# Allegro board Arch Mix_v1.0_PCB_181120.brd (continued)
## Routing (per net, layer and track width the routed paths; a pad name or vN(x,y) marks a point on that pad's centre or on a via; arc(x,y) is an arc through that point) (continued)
SEMC_A10: length 35
  TOP w0.127: U8.G2 36.48,21.66 34.83,21.66 34.7,21.52 30.42,21.52 24.24,15.35 23.05,15.35 22.86,15.54 22.86,15.73 22.73,15.86 22.48,15.86 22.35,15.73 22.35,15.43 22.22,15.3 21.97,15.3 21.84,15.43 21.84,15.73 21.71,15.86 21.46,15.86 21.33,15.73 21.33,15.44 21.12,15.22 16.27,15.22 15.87,15.62 15.69,15.62 15.36,15.3 15.18,15.3 15,15.48 15,15.66 15.33,15.98 15.33,16.16 14.86,16.63 14.68,16.63 14.48,16.43 14.3,16.43 14.12,16.61 14.12,16.79 14.32,16.99 14.32,17.17 13.91,17.58 13.73,17.58 13.15,17 12.97,17 12.79,17.18 12.79,17.36 13.37,17.94 13.37,18.12 13.21,18.29 U4.H9
SEMC_A11: length 34.8
  TOP w0.127: U4.G2 13.58,26.39 13.58,26.6 13.58,26.6 13.58,28.64 14.59,29.65 28.23,29.65 28.38,29.5 28.38,29.29 28.53,29.14 28.74,29.14 28.89,29.29 28.89,29.5 29.04,29.65 29.43,29.65 29.58,29.5 29.58,29.29 29.73,29.14 29.94,29.14 30.09,29.29 30.09,29.5 30.24,29.65 30.45,29.65 30.6,29.5 30.6,29.29 30.74,29.14 30.96,29.14 31.1,29.29 31.1,29.5 31.25,29.65 31.46,29.65 31.61,29.5 31.61,29.29 31.76,29.14 31.97,29.14 32.12,29.29 32.12,29.5 32.27,29.65 32.48,29.65 32.63,29.5 32.63,29.29 32.78,29.14 32.99,29.14 33.14,29.29 33.14,29.5 33.28,29.65 33.5,29.65 33.64,29.5 33.64,29.29 33.79,29.14 34,29.14 34.15,29.29 34.15,29.5 34.3,29.65 34.65,29.65 37.77,26.53 37.77,24.92 U8.B4
SEMC_A12: length 34.5
  TOP w0.127: U4.G1 14.01,27.93 15.35,29.27 15.85,29.27 16,29.12 16,28.91 16.15,28.76 16.36,28.76 16.5,28.91 16.5,29.12 16.65,29.27 16.86,29.27 17.01,29.12 17.01,28.91 17.16,28.76 17.37,28.76 17.52,28.91 17.52,29.12 17.67,29.27 17.88,29.27 18.03,29.12 18.03,28.91 18.18,28.76 18.39,28.76 18.54,28.91 18.54,29.12 18.69,29.27 18.9,29.27 19.04,29.12 19.04,28.91 19.19,28.76 19.4,28.76 19.55,28.91 19.55,29.12 19.7,29.27 19.91,29.27 20.06,29.12 20.06,28.91 20.21,28.76 20.42,28.76 20.57,28.91 20.57,29.12 20.72,29.27 20.93,29.27 21.08,29.12 21.08,28.91 21.23,28.76 21.44,28.76 21.58,28.91 21.58,29.12 21.73,29.27 22.58,29.27 22.84,29.02 23.09,29.02 23.34,29.27 23.85,29.27 24,29.12 24,28.91 24.15,28.76 24.36,28.76 24.51,28.91 24.51,29.12 24.65,29.27 24.86,29.27 25.01,29.12 25.01,28.91 25.16,28.76 25.37,28.76 25.52,28.91 25.52,29.12 25.67,29.27 25.88,29.27 26.03,29.12 26.03,28.91 26.18,28.76 26.39,28.76 26.54,28.91 26.54,29.12 26.69,29.27 26.9,29.27 27.05,29.12 27.05,28.91 27.19,28.76 27.4,28.76 27.55,28.91 27.55,29.12 27.7,29.27 27.91,29.27 28.06,29.12 28.06,28.91 28.21,28.76 34.99,28.76 37.45,26.3 U8.A3
SEMC_BA0: length 35.1
  TOP w0.127: U4.G7 14.01,22.67 14.14,22.79 22.34,22.79 23.49,23.94 27.17,23.94 27.32,24.09 27.32,24.8 27.47,24.95 27.68,24.95 27.83,24.8 27.83,24.09 27.98,23.94 28.3,23.94 28.45,24.09 28.45,24.8 28.6,24.95 28.81,24.95 28.95,24.8 28.95,24.09 29.1,23.94 29.31,23.94 29.46,24.09 29.46,24.8 29.61,24.95 29.82,24.95 29.97,24.8 29.97,24.09 30.12,23.94 30.33,23.94 30.48,24.09 30.48,24.8 30.63,24.95 30.84,24.95 30.99,24.8 30.99,24.09 31.14,23.94 31.35,23.94 31.49,24.09 31.49,24.8 31.64,24.95 31.85,24.95 32,24.8 32,24.09 32.15,23.94 32.36,23.94 32.51,24.09 32.51,24.8 32.66,24.95 32.87,24.95 33.02,24.8 33.02,24.09 33.17,23.94 33.38,23.94 33.53,24.09 33.53,24.8 33.68,24.95 33.89,24.95 34.03,24.8 34.03,24.09 34.18,23.94 U8.C1
SEMC_BA1: length 35.5
  TOP w0.127: U4.G8 13.64,20.79 13.64,18.41 16.24,15.81 16.6,15.81 16.75,15.96 16.75,16.04 16.9,16.19 18.38,16.19 18.53,16.04 18.53,15.83 18.68,15.68 18.89,15.68 19.04,15.83 19.04,16.04 19.19,16.19 20.16,16.19 20.31,16.04 20.31,15.83 20.46,15.68 20.67,15.68 20.82,15.83 20.82,16.04 20.97,16.19 22.85,16.19 23.33,16.68 24.43,16.68 24.6,16.51 24.81,16.51 24.96,16.66 24.96,16.87 24.79,17.04 24.79,17.25 24.94,17.4 25.15,17.4 25.32,17.23 25.53,17.23 25.68,17.37 25.68,17.58 25.51,17.75 25.51,17.97 25.66,18.11 25.87,18.11 26.04,17.94 26.25,17.94 26.4,18.09 26.4,18.3 26.23,18.47 26.23,18.68 26.38,18.83 26.59,18.83 26.76,18.66 26.97,18.66 27.12,18.81 27.12,19.02 26.95,19.19 26.95,19.4 27.1,19.55 27.31,19.55 27.48,19.38 27.69,19.38 27.84,19.53 27.84,19.74 27.67,19.91 27.67,20.12 27.82,20.27 28.03,20.27 28.2,20.1 28.41,20.1 28.56,20.25 28.56,20.46 28.39,20.63 28.39,20.84 28.54,20.99 28.75,20.99 28.92,20.82 29.13,20.82 29.28,20.97 29.28,21.18 29.11,21.35 29.11,21.56 29.38,21.83 34.28,21.83 34.44,21.99 U8.F1
SEMC_CAS: length 34.4
  TOP w0.127: U4.F7 15.23,21.54 15.23,19.75 15.99,18.98 21.71,18.98 22.98,20.26 22.98,20.47 22.55,20.89 22.55,21.1 22.7,21.25 22.91,21.25 23.34,20.82 23.55,20.82 23.77,21.05 23.77,21.26 23.09,21.94 23.09,22.15 23.24,22.3 23.45,22.3 24.13,21.62 24.34,21.62 24.49,21.77 24.49,21.98 23.81,22.66 23.81,22.87 23.96,23.02 24.17,23.02 24.85,22.34 25.06,22.34 25.23,22.51 25.23,22.72 24.74,23.21 24.74,23.42 24.89,23.57 25.1,23.57 25.59,23.08 25.8,23.08 26.15,23.43 35.23,23.43 35.42,23.62 37.12,23.62 U8.D3
SEMC_CKE: length 36.1
  TOP w0.127: U8.A2 36.8,25.48 35.04,27.24 34.53,27.24 34.38,27.39 34.38,27.73 34.23,27.87 34.02,27.87 33.87,27.73 33.87,27.39 33.72,27.24 33.51,27.24 33.36,27.39 33.36,27.73 33.22,27.87 33.01,27.87 32.86,27.73 32.86,27.39 32.71,27.24 32.5,27.24 32.35,27.39 32.35,27.73 32.2,27.87 31.99,27.87 31.84,27.73 31.84,27.39 31.69,27.24 31.48,27.24 31.33,27.39 31.33,27.73 31.18,27.87 30.97,27.87 30.82,27.73 30.82,27.39 30.68,27.24 30.47,27.24 30.32,27.39 30.32,27.73 30.17,27.87 29.96,27.87 29.81,27.73 29.81,27.39 29.66,27.24 29.45,27.24 29.3,27.39 29.3,27.73 29.15,27.87 28.94,27.87 28.79,27.73 28.79,27.39 28.64,27.24 28.43,27.24 28.28,27.39 28.28,27.73 28.14,27.87 27.93,27.87 27.78,27.73 27.78,27.39 27.63,27.24 27.42,27.24 27.27,27.39 27.27,27.73 27.12,27.87 26.91,27.87 26.76,27.73 26.76,27.39 26.61,27.24 26.4,27.24 26.25,27.39 26.25,27.73 26.1,27.87 25.89,27.87 25.74,27.73 25.74,27.39 25.6,27.24 25.39,27.24 25.24,27.39 25.24,27.73 25.09,27.87 24.88,27.87 24.73,27.73 24.73,27.39 24.58,27.24 22.15,27.24 21.58,26.67 21.58,24.83 21.07,24.32 15.65,24.32 U4.F3 v2(14.41,25.56)
  BOTTOM w0.102: v2(14.41,25.56) 14.37,25.59 R129.1
SEMC_CLK: length 3.3
  TOP w0.127: R15.1 37.12,25.92 37.12,24.92 U8.B3
SEMC_CS0: length 35.8
  TOP w0.127: U4.G9 14.01,19.31 v2(14.21,19.11) 14.21,18.48 16.12,16.57 16.52,16.57 16.67,16.72 16.67,16.93 16.82,17.08 17.03,17.08 17.17,16.93 17.17,16.72 17.32,16.57 17.53,16.57 17.68,16.72 17.68,16.93 17.83,17.08 18.04,17.08 18.19,16.93 18.19,16.72 18.34,16.57 18.55,16.57 18.7,16.72 18.7,16.93 18.85,17.08 19.06,17.08 19.21,16.93 19.21,16.72 19.36,16.57 19.57,16.57 19.71,16.72 19.71,16.93 19.86,17.08 20.07,17.08 20.22,16.93 20.22,16.72 20.37,16.57 20.58,16.57 20.73,16.72 20.73,16.93 20.88,17.08 21.09,17.08 21.24,16.93 21.24,16.72 21.39,16.57 21.6,16.57 21.75,16.72 21.75,16.93 21.9,17.08 22.11,17.08 22.25,16.93 22.25,16.72 22.4,16.57 22.72,16.57 23.38,17.23 23.72,17.23 23.82,17.12 24.04,17.12 24.18,17.27 24.18,17.48 24.08,17.59 24.08,17.8 24.23,17.95 24.44,17.95 24.54,17.84 24.75,17.84 24.9,17.99 24.9,18.2 24.8,18.31 24.8,18.52 24.95,18.67 25.16,18.67 25.26,18.56 25.47,18.56 25.62,18.71 25.62,18.92 25.51,19.03 25.51,19.24 25.66,19.39 25.87,19.39 25.98,19.28 26.19,19.28 26.34,19.43 26.34,19.64 26.23,19.75 26.23,19.96 26.38,20.11 26.59,20.11 26.7,20 26.91,20 27.06,20.15 27.06,20.36 26.95,20.47 26.95,20.68 27.1,20.82 27.31,20.82 27.42,20.72 27.63,20.72 27.78,20.87 27.78,21.08 27.67,21.18 27.67,21.39 27.82,21.54 28.03,21.54 28.14,21.44 28.35,21.44 28.5,21.59 28.5,21.8 28.39,21.9 28.39,22.11 28.56,22.29 35.79,22.29 U8.E1
  BOTTOM w0.127: R127.2 13.96,19.36 v2(14.21,19.11)
SEMC_D0: length 34.6
  TOP w0.127: U8.E3 v1(37.12,22.97) ; U4.A8 v2(19.21,20.76)
  BOTTOM w0.127: v2(19.21,20.76) 19.67,21.22 19.67,24.32 19.93,24.57 20.12,24.57 20.27,24.72 20.27,25.57 20.42,25.71 20.63,25.71 20.78,25.57 20.78,24.72 20.92,24.57 21.14,24.57 21.28,24.72 21.28,25.57 21.43,25.71 21.64,25.71 21.79,25.57 21.79,24.72 21.94,24.57 22.15,24.57 22.3,24.72 22.3,25.57 22.45,25.71 22.66,25.71 22.81,25.57 22.81,24.72 22.96,24.57 23.17,24.57 23.32,24.72 23.32,25.57 23.46,25.71 23.68,25.71 23.82,25.57 23.82,24.72 23.97,24.57 24.18,24.57 24.33,24.72 24.33,25.57 24.48,25.71 24.69,25.71 24.84,25.57 24.84,24.72 24.99,24.57 25.2,24.57 25.35,24.72 25.35,25.57 25.5,25.71 25.71,25.71 25.86,25.57 25.86,24.72 26,24.57 33.64,24.57 34.53,23.68 35.8,23.68 36.52,22.97 v1(37.12,22.97)
SEMC_D1: length 34.5
  TOP w0.127: U4.B9 v2(18.41,19.96) ; U8.F3 v1(37.12,22.32)
  BOTTOM w0.102: 35.13,22.92 36.06,21.99 36.61,21.99 36.93,22.32 v1(37.12,22.32)
  BOTTOM w0.127: v2(18.41,19.96) 18.87,19.49 19.55,19.49 20.43,20.38 20.43,20.67 20.58,20.82 20.79,20.82 20.94,20.97 20.94,21.18 20.79,21.33 20.58,21.33 20.43,21.48 20.43,21.68 20.58,21.83 21.43,21.83 21.58,21.98 21.58,22.19 21.43,22.34 20.58,22.34 20.43,22.48 20.43,22.79 20.56,22.92 20.79,22.92 20.94,23.07 20.94,23.66 21.09,23.81 21.3,23.81 21.44,23.66 21.44,23.07 21.59,22.92 21.8,22.92 21.95,23.07 21.95,23.66 22.1,23.81 22.31,23.81 22.46,23.66 22.46,23.07 22.61,22.92 22.82,22.92 22.97,23.07 22.97,23.66 23.12,23.81 23.33,23.81 23.48,23.66 23.48,23.07 23.63,22.92 23.84,22.92 23.98,23.07 23.98,23.66 24.13,23.81 24.34,23.81 24.49,23.66 24.49,23.07 24.64,22.92 24.85,22.92 25,23.07 25,23.66 25.15,23.81 25.36,23.81 25.51,23.66 25.51,23.07 25.66,22.92 25.87,22.92 26.02,23.07 26.02,23.66 26.17,23.81 26.38,23.81 26.52,23.66 26.52,23.07 26.67,22.92 35.13,22.92
SEMC_D2: length 34.3
  TOP w0.127: U8.F4 v1(37.77,22.32) ; U4.B8 v2(18.41,20.76)
  BOTTOM w0.102: 36.18,22.64 37.45,22.64 v1(37.77,22.32)
  BOTTOM w0.127: 36.18,22.64 35.52,23.3 34.22,23.3 34.07,23.45 34.07,23.66 33.93,23.81 33.72,23.81 33.57,23.66 33.57,23.45 33.42,23.3 33.19,23.3 33.04,23.45 33.04,24.04 32.89,24.19 32.68,24.19 32.53,24.04 32.53,23.45 32.38,23.3 32.19,23.3 32.04,23.45 32.04,24.04 31.89,24.19 31.68,24.19 31.53,24.04 31.53,23.45 31.39,23.3 31.18,23.3 31.03,23.45 31.03,24.04 30.88,24.19 30.67,24.19 30.52,24.04 30.52,23.45 30.37,23.3 30.16,23.3 30.01,23.45 30.01,24.04 29.86,24.19 29.65,24.19 29.5,24.04 29.5,23.45 29.35,23.3 29.14,23.3 28.99,23.45 28.99,24.04 28.85,24.19 28.64,24.19 28.49,24.04 28.49,23.45 28.34,23.3 28.13,23.3 27.98,23.45 27.98,24.04 27.83,24.19 27.62,24.19 27.47,24.04 27.47,23.45 27.32,23.3 27.11,23.3 26.96,23.45 26.96,24.04 26.81,24.19 20.43,24.19 20.05,23.81 20.05,20.76 19.66,20.37 18.8,20.37 v2(18.41,20.76)
SEMC_D3: length 34.3
  TOP w0.127: U8.G4 v1(37.77,21.67) ; U4.C9 v2(17.61,19.96)
  BOTTOM w0.102: v1(37.77,21.67) 37.45,21.99 36.99,21.99 36.74,21.74 35.84,21.74 35.04,22.54
  BOTTOM w0.127: v2(17.61,19.96) 18.49,19.07 19.63,19.07 20.43,19.87 20.62,19.87 20.77,20.02 20.77,20.23 20.92,20.38 21.13,20.38 21.28,20.23 21.28,20.12 21.4,19.99 21.96,19.99 22.09,20.12 22.09,20.23 22.23,20.38 22.83,20.38 22.97,20.53 22.97,20.74 22.83,20.88 22.23,20.88 22.09,21.03 22.09,21.24 22.23,21.39 22.7,21.39 22.85,21.54 22.85,21.75 22.7,21.9 22.23,21.9 22.09,22.05 22.09,22.29 22.34,22.54 23.3,22.54 23.45,22.39 23.45,21.16 23.6,21.02 23.81,21.02 23.96,21.16 23.96,22.39 24.11,22.54 24.32,22.54 24.47,22.39 24.47,21.42 24.61,21.27 24.82,21.27 24.97,21.42 24.97,22.39 25.12,22.54 25.88,22.54 26.03,22.39 26.03,21.8 26.18,21.65 26.39,21.65 26.54,21.8 26.54,22.39 26.69,22.54 35.04,22.54
SEMC_D4: length 34.5
  TOP w0.127: U4.C8 v2(17.61,20.76) ; U8.F2 v1(37.12,21.67)
  BOTTOM w0.102: v1(37.12,21.67) 37.02,21.67 36.84,21.48 35.59,21.48 35.42,21.65
  BOTTOM w0.127: v2(17.61,20.76) 17.2,20.34 17.2,19.55 18.02,18.73 22.52,18.73 22.66,18.88 22.66,19.77 22.76,19.86 23.04,19.86 23.17,19.74 23.17,18.88 23.32,18.73 23.99,18.73 24.14,18.88 24.14,19.09 23.78,19.46 23.78,19.67 23.93,19.81 24.14,19.81 24.5,19.45 24.71,19.45 24.86,19.6 24.86,19.81 24.5,20.17 24.5,20.38 24.65,20.53 24.86,20.53 25.22,20.17 25.43,20.17 25.62,20.36 25.62,20.57 25.26,20.93 25.26,21.14 25.41,21.29 25.62,21.29 25.98,20.93 26.19,20.93 26.91,21.65 27.31,21.65 27.46,21.8 27.46,22.01 27.61,22.16 27.82,22.16 27.97,22.01 27.97,21.8 28.11,21.65 28.32,21.65 28.47,21.8 28.47,22.01 28.62,22.16 28.83,22.16 28.98,22.01 28.98,21.8 29.13,21.65 29.34,21.65 29.49,21.8 29.49,22.01 29.64,22.16 29.85,22.16 30,22.01 30,21.8 30.15,21.65 30.36,21.65 30.51,21.8 30.51,22.01 30.65,22.16 30.86,22.16 31.01,22.01 31.01,21.8 31.16,21.65 31.37,21.65 31.52,21.8 31.52,22.01 31.67,22.16 31.88,22.16 32.03,22.01 32.03,21.8 32.18,21.65 32.39,21.65 32.54,21.8 32.54,22.01 32.69,22.16 32.9,22.16 33.05,22.01 33.05,21.8 33.19,21.65 33.4,21.65 33.55,21.8 33.55,22.01 33.7,22.16 33.91,22.16 34.06,22.01 34.06,21.8 34.21,21.65 35.42,21.65
SEMC_D5: length 35.1
  TOP w0.127: U8.G5 v1(38.42,21.02) ; U4.D9 v2(16.81,19.96)
  BOTTOM w0.102: 35.33,21.23 37.56,21.23 37.77,21.02 v1(38.42,21.02)
  BOTTOM w0.127: 35.33,21.23 34.18,21.23 34.03,21.08 34.03,20.78 33.88,20.63 33.67,20.63 33.52,20.78 33.52,21.08 33.37,21.23 33.16,21.23 33.01,21.08 33.01,20.78 32.86,20.63 32.65,20.63 32.5,20.78 32.5,21.08 32.35,21.23 32.14,21.23 31.99,21.08 31.99,20.78 31.85,20.63 31.64,20.63 31.49,20.78 31.49,21.08 31.34,21.23 31.13,21.23 30.98,21.08 30.98,20.78 30.83,20.63 30.62,20.63 30.47,20.78 30.47,21.08 30.32,21.23 30.11,21.23 29.96,21.08 29.96,20.78 29.81,20.63 29.6,20.63 29.45,20.78 29.45,21.08 29.31,21.23 29.1,21.23 28.95,21.08 28.95,20.78 28.8,20.63 28.59,20.63 28.44,20.78 28.44,21.08 28.29,21.23 28.08,21.23 27.93,21.08 27.93,20.78 27.78,20.63 27.57,20.63 27.42,20.78 27.42,21.08 27.27,21.23 27,21.23 23.74,17.97 23.36,17.97 23.21,18.12 23.21,18.2 23.06,18.35 22.85,18.35 22.7,18.2 22.7,18.12 22.56,17.97 22.34,17.97 22.2,18.12 22.2,18.2 22.05,18.35 21.84,18.35 21.69,18.2 21.69,18.12 21.54,17.97 21.33,17.97 21.18,18.12 21.18,18.2 21.03,18.35 20.82,18.35 20.67,18.2 20.67,18.12 20.52,17.97 20.31,17.97 20.16,18.12 20.16,18.2 20.02,18.35 19.8,18.35 19.66,18.2 19.66,18.12 19.51,17.97 19.3,17.97 19.15,18.12 19.15,18.2 19,18.35 18.79,18.35 18.64,18.2 18.64,18.12 18.49,17.97 18.28,17.97 18.13,18.12 18.13,18.2 17.98,18.35 17.77,18.35 17.62,18.2 17.62,18.12 17.48,17.97 17.01,17.97 16.81,18.17 16.81,18.33 16.96,18.48 17.24,18.48 17.39,18.63 17.39,18.84 17.24,18.98 16.96,18.98 16.81,19.13 v2(16.81,19.96)
SEMC_D6: length 34.8
  TOP w0.127: U8.H5 v1(38.42,20.37) ; U4.D8 v2(16.81,20.76)
  BOTTOM w0.102: 34.34,20.44 34.79,20.89 35.42,20.89 35.51,20.98 37.33,20.98 37.62,20.69 38.1,20.69 v1(38.42,20.37)
  BOTTOM w0.127: v2(16.81,20.76) 16.42,20.37 16.42,19.39 16.27,19.24 15.88,19.24 15.74,19.09 15.74,18.88 15.88,18.73 16.27,18.73 16.42,18.58 16.42,18.37 16.27,18.23 15.88,18.23 15.74,18.08 15.74,17.33 15.99,17.08 16.42,17.08 16.57,17.23 16.57,17.44 16.72,17.59 16.93,17.59 17.08,17.44 17.08,17.23 17.23,17.08 17.44,17.08 17.59,17.23 17.59,17.44 17.73,17.59 17.94,17.59 18.09,17.44 18.09,17.23 18.24,17.08 18.45,17.08 18.6,17.23 18.6,17.44 18.75,17.59 18.96,17.59 19.11,17.44 19.11,17.23 19.26,17.08 19.47,17.08 19.62,17.23 19.62,17.44 19.77,17.59 19.98,17.59 20.13,17.44 20.13,17.23 20.27,17.08 20.48,17.08 20.63,17.23 20.63,17.44 20.78,17.59 20.99,17.59 21.14,17.44 21.14,17.23 21.29,17.08 21.5,17.08 21.65,17.23 21.65,17.44 21.8,17.59 22.01,17.59 22.16,17.44 22.16,17.23 22.31,17.08 23.48,17.08 26.73,20.33 34.23,20.33 34.34,20.44
SEMC_D7: length 34.3
  TOP w0.127: U8.H4 v1(37.77,20.37) ; U4.E9 v2(16.01,19.96)
  BOTTOM w0.102: 34.4,20 34.91,20.51 35.54,20.51 35.72,20.69 37.26,20.69 37.58,20.37 v1(37.77,20.37)
  BOTTOM w0.127: 34.4,20 28.18,20 27.78,19.6 27.57,19.6 27.27,19.9 27.06,19.9 26.91,19.75 26.91,19.54 27.21,19.24 27.21,19.03 27.06,18.88 26.85,18.88 26.43,19.3 26.22,19.3 26.07,19.15 26.07,18.94 26.49,18.52 26.49,18.31 26.34,18.16 26.13,18.16 25.71,18.58 25.5,18.58 25.35,18.44 25.35,18.23 25.77,17.8 25.77,17.59 25.62,17.44 25.41,17.44 24.99,17.87 24.78,17.87 24.63,17.72 24.63,17.51 25.05,17.08 25.05,16.87 24.88,16.7 15.48,16.7 15.1,17.08 15.1,19.05 v2(16.01,19.96)
SEMC_D8: length 34.6
  TOP w0.127: U8.C6 v1(39.07,24.27) ; U4.E1 v2(16.01,27.16)
  BOTTOM w0.102: v1(39.07,24.27) 39.07,24.66 38.86,24.87 38.86,25.2 38.46,25.61 38.46,26.24
  BOTTOM w0.127: v2(16.01,27.16) 15.48,27.68 15.48,27.85 15.63,28 15.84,28 15.99,28.14 15.99,28.36 15.84,28.5 15.63,28.5 15.48,28.65 15.48,28.86 15.63,29.01 15.84,29.01 15.99,29.16 15.99,29.37 15.84,29.52 15.63,29.52 15.48,29.67 15.48,29.88 15.63,30.03 15.84,30.03 15.99,30.18 15.99,30.39 15.84,30.54 15.63,30.54 15.48,30.68 15.48,30.92 15.74,31.18 33.9,31.18 38.46,26.62 38.46,26.24
SEMC_D9: length 35
  TOP w0.127: U4.D2 v2(16.81,26.36) ; U8.C5 v1(38.42,24.27)
  BOTTOM w0.102: 38.09,26.35 38.09,24.78 38.42,24.44 v1(38.42,24.27)
  BOTTOM w0.127: 38.09,26.35 38.09,26.48 33.77,30.79 32.81,30.79 32.66,30.65 32.66,30.44 32.51,30.29 32.3,30.29 32.15,30.44 32.15,30.65 32,30.79 31.79,30.79 31.64,30.65 31.64,30.44 31.49,30.29 31.28,30.29 31.13,30.44 31.13,30.65 30.98,30.79 30.77,30.79 30.63,30.65 30.63,30.44 30.48,30.29 30.27,30.29 30.12,30.44 30.12,30.65 29.97,30.79 29.76,30.79 29.61,30.65 29.61,30.44 29.46,30.29 29.25,30.29 29.1,30.44 29.1,30.65 28.95,30.79 28.74,30.79 28.59,30.65 28.59,30.44 28.44,30.29 28.23,30.29 28.09,30.44 28.09,30.65 27.94,30.79 27.73,30.79 27.58,30.65 27.58,30.44 27.43,30.29 27.22,30.29 27.07,30.44 27.07,30.65 26.92,30.79 17.13,30.79 16.4,30.06 16.4,26.77 v2(16.81,26.36)
SEMC_D10: length 34.7
  TOP w0.127: U4.D1 v2(16.81,27.16) ; U8.D5 v1(38.42,23.62)
  BOTTOM w0.102: 37.78,25.89 37.78,24.75 38.1,24.43 38.1,23.94 v1(38.42,23.62)
  BOTTOM w0.127: 37.78,25.89 33.77,29.91 26.55,29.91 26.4,30.05 26.4,30.27 26.25,30.41 26.04,30.41 25.89,30.27 25.89,30.05 25.74,29.91 25.53,29.91 25.38,30.05 25.38,30.27 25.23,30.41 25.02,30.41 24.87,30.27 24.87,30.05 24.72,29.91 24.51,29.91 24.36,30.05 24.36,30.27 24.22,30.41 24.01,30.41 23.86,30.27 23.86,30.05 23.71,29.91 23.5,29.91 23.35,30.05 23.35,30.27 23.2,30.41 22.99,30.41 22.84,30.27 22.84,30.05 22.69,29.91 22.48,29.91 22.33,30.05 22.33,30.27 22.18,30.41 21.97,30.41 21.82,30.27 21.82,30.05 21.68,29.91 21.47,29.91 21.32,30.05 21.32,30.27 21.17,30.41 20.96,30.41 20.81,30.27 20.81,30.05 20.66,29.91 20.45,29.91 20.3,30.05 20.3,30.27 20.15,30.41 19.94,30.41 19.79,30.27 19.79,30.05 19.64,29.91 19.43,29.91 19.28,30.05 19.28,30.27 19.14,30.41 18.93,30.41 18.78,30.27 18.78,30.05 18.63,29.91 18.42,29.91 18.27,30.05 18.27,30.27 18.12,30.41 17.91,30.41 17.76,30.27 17.76,30.05 17.61,29.91 17.26,29.91 16.81,29.45 v2(16.81,27.16)
SEMC_D11: length 34.5
  TOP w0.127: U8.C4 v1(37.77,24.27) ; U4.C2 v2(17.61,26.36)
  BOTTOM w0.102: v1(37.77,24.27) 37.77,24.44 37.5,24.71 37.5,25.28 36.44,26.35
  BOTTOM w0.127: 36.44,26.35 34.02,28.76 33.66,28.76 33.51,28.91 33.51,29.38 33.36,29.52 33.15,29.52 33,29.38 33,28.91 32.85,28.76 32.56,28.76 32.41,28.91 32.41,29.38 32.26,29.52 32.05,29.52 31.9,29.38 31.9,28.91 31.75,28.76 31.54,28.76 31.39,28.91 31.39,29.38 31.25,29.52 31.04,29.52 30.89,29.38 30.89,28.91 30.74,28.76 30.53,28.76 30.38,28.91 30.38,29.38 30.23,29.52 30.02,29.52 29.87,29.38 29.87,28.91 29.72,28.76 29.51,28.76 29.36,28.91 29.36,29.38 29.21,29.52 29,29.52 28.85,29.38 28.85,28.91 28.71,28.76 28.5,28.76 28.35,28.91 28.35,29.38 28.2,29.52 27.99,29.52 27.84,29.38 27.84,28.91 27.69,28.76 27.48,28.76 27.33,28.91 27.33,29.38 27.18,29.52 17.77,29.52 17.2,28.95 17.2,26.77 v2(17.61,26.36)
SEMC_D12: length 35
  TOP w0.127: U8.D4 v1(37.77,23.62) ; U4.C1 v2(17.61,27.16)
  BOTTOM w0.102: v1(37.77,23.62) 37.45,23.94 37.45,24.4 37.2,24.65 37.2,24.83 35.67,26.35
  BOTTOM w0.127: v2(17.61,27.16) 17.61,28.22 17.77,28.38 18.11,28.38 18.26,28.53 18.26,28.87 18.41,29.02 18.62,29.02 18.77,28.87 18.77,28.53 18.92,28.38 19.16,28.38 19.31,28.53 19.31,29 19.46,29.14 19.67,29.14 19.82,29 19.82,28.53 19.97,28.38 20.18,28.38 20.33,28.53 20.33,29 20.47,29.14 20.68,29.14 20.83,29 20.83,28.53 20.98,28.38 21.19,28.38 21.34,28.53 21.34,29 21.49,29.14 21.7,29.14 21.85,29 21.85,28.53 22,28.38 22.21,28.38 22.36,28.53 22.36,29 22.51,29.14 22.72,29.14 22.87,29 22.87,28.53 23.01,28.38 23.22,28.38 23.37,28.53 23.37,29 23.52,29.14 23.73,29.14 23.88,29 23.88,28.53 24.03,28.38 24.24,28.38 24.39,28.53 24.39,29 24.54,29.14 24.75,29.14 24.9,29 24.9,28.53 25.05,28.38 25.26,28.38 25.41,28.53 25.41,29 25.55,29.14 25.76,29.14 25.91,29 25.91,28.53 26.06,28.38 26.27,28.38 26.42,28.53 26.42,29 26.57,29.14 26.78,29.14 26.93,29 26.93,28.53 27.08,28.38 33.64,28.38 35.67,26.35
SEMC_D13: length 34.4
  TOP w0.127: U8.E5 v1(38.42,22.97) ; U4.B2 v2(18.41,26.36)
  BOTTOM w0.102: 34.4,25.59 35.55,24.44 36.46,24.44 37.62,23.29 38.1,23.29 v1(38.42,22.97)
  BOTTOM w0.127: 34.4,25.59 33.52,26.48 25.93,26.48 25.78,26.63 25.78,27.47 25.63,27.62 25.42,27.62 25.27,27.47 25.27,26.63 25.12,26.48 24.91,26.48 24.77,26.63 24.77,27.47 24.62,27.62 24.41,27.62 24.26,27.47 24.26,26.63 24.11,26.48 23.9,26.48 23.75,26.63 23.75,27.47 23.6,27.62 23.39,27.62 23.24,27.47 23.24,26.63 23.09,26.48 22.88,26.48 22.73,26.63 22.73,27.47 22.58,27.62 22.37,27.62 22.23,27.47 22.23,26.63 22.08,26.48 21.87,26.48 21.72,26.63 21.72,27.47 21.57,27.62 21.36,27.62 21.21,27.47 21.21,26.63 21.06,26.48 20.85,26.48 20.7,26.63 20.7,27.47 20.55,27.62 20.34,27.62 20.19,27.47 20.19,26.63 20.04,26.48 19.8,26.48 19.51,26.77 18.82,26.77 v2(18.41,26.36)
SEMC_D14: length 34.7
  TOP w0.127: U4.B1 v2(18.41,27.16) ; U8.C3 v1(37.12,24.27)
  BOTTOM w0.102: 34.79,25.97 35.95,24.81 36.58,24.81 v1(37.12,24.27)
  BOTTOM w0.127: 34.79,25.97 33.9,26.86 33.58,26.86 33.43,27.01 33.43,27.34 33.29,27.49 33.08,27.49 32.93,27.34 32.93,27.01 32.78,26.86 32.54,26.86 32.39,27.01 32.39,27.85 32.24,28 32.03,28 31.88,27.85 31.88,27.01 31.74,26.86 31.44,26.86 31.29,27.01 31.29,27.85 31.14,28 30.93,28 30.78,27.85 30.78,27.01 30.64,26.86 30.43,26.86 30.28,27.01 30.28,27.85 30.13,28 29.92,28 29.77,27.85 29.77,27.01 29.62,26.86 29.41,26.86 29.26,27.01 29.26,27.85 29.11,28 28.9,28 28.75,27.85 28.75,27.01 28.6,26.86 28.39,26.86 28.24,27.01 28.24,27.85 28.1,28 27.89,28 27.74,27.85 27.74,27.01 27.59,26.86 27.38,26.86 27.23,27.01 27.23,27.85 27.08,28 26.87,28 26.72,27.85 26.72,27.01 26.57,26.86 26.36,26.86 26.21,27.01 26.21,27.85 26.06,28 19.25,28 v2(18.41,27.16)
SEMC_D15: length 34.3
  TOP w0.127: U8.E4 v1(37.77,22.97) ; U4.A2 v2(19.21,26.36)
  BOTTOM w0.102: v1(37.77,22.97) 37.58,22.97 37.26,23.29 36.97,23.29 36.19,24.06 34.79,24.06 34.28,24.57
  BOTTOM w0.127: 34.28,24.57 34.28,25.08 33.64,25.71 33.25,25.71 33.1,25.57 33.1,25.1 32.95,24.95 32.71,24.95 32.56,25.1 32.56,25.95 32.41,26.1 32.2,26.1 32.05,25.95 32.05,25.1 31.9,24.95 31.64,24.95 31.49,25.1 31.49,25.95 31.34,26.1 31.13,26.1 30.99,25.95 30.99,25.1 30.84,24.95 30.63,24.95 30.48,25.1 30.48,25.95 30.33,26.1 30.12,26.1 29.97,25.95 29.97,25.1 29.82,24.95 29.61,24.95 29.46,25.1 29.46,25.95 29.31,26.1 29.1,26.1 28.95,25.95 28.95,25.1 28.8,24.95 28.59,24.95 28.45,25.1 28.45,25.95 28.3,26.1 28.09,26.1 27.94,25.95 27.94,25.1 27.79,24.95 27.58,24.95 27.43,25.1 27.43,25.95 27.28,26.1 27.07,26.1 26.92,25.95 26.92,25.1 26.77,24.95 26.56,24.95 26.41,25.1 26.41,25.95 26.26,26.1 19.47,26.1 v2(19.21,26.36)
SEMC_DM0: length 34.5
  TOP w0.127: U8.H3 v1(37.12,20.37) ; U4.E8 v2(16.01,20.76)
  BOTTOM w0.102: v1(37.12,20.37) 35.79,20.37 35.55,20.13 34.91,20.13 34.4,19.62
  BOTTOM w0.127: v2(16.01,20.76) 14.72,19.47 14.72,16.82 15.23,16.32 26.15,16.32 26.3,16.46 26.3,16.67 25.93,17.03 25.93,17.24 26.08,17.39 26.29,17.39 26.66,17.03 26.87,17.03 27.01,17.18 27.01,17.39 26.65,17.75 26.65,17.96 26.8,18.11 27.01,18.11 27.37,17.75 27.58,17.75 27.73,17.9 27.73,18.11 27.37,18.47 27.37,18.68 27.52,18.83 27.73,18.83 28.09,18.47 28.3,18.47 28.5,18.66 28.5,18.87 28.26,19.11 28.26,19.32 28.41,19.47 28.62,19.47 28.86,19.23 29.07,19.23 29.45,19.62 34.4,19.62
SEMC_DM1: length 34.4
  TOP w0.127: U4.F1 v2(15.21,27.16) ; U8.D6 v1(39.07,23.62)
  BOTTOM w0.102: v1(39.07,23.62) 39.07,23.78 39.4,24.1 39.4,24.76 39.1,25.06 39.1,25.4 38.81,25.7 38.81,26.35
  BOTTOM w0.127: v2(15.21,27.16) 15.1,27.26 15.1,31.05 15.61,31.56 34.02,31.56 38.81,26.77 38.81,26.35
SEMC_DQS: length 4.8
  TOP w0.127: U8.B7 39.78,24.86 39.78,25.06 39.73,25.11 39.73,25.68 39.36,26.05 39.36,26.89 39.95,27.48 39.95,28.04 39.66,28.33 C22.1
SEMC_RAS: length 34.3
  TOP w0.127: U8.D2 36.48,22.97 35.85,22.97 35.55,22.67 27.42,22.67 27.24,22.49 27.24,22.28 27.54,21.98 27.54,21.77 27.39,21.62 27.18,21.62 26.88,21.92 26.67,21.92 26.52,21.77 26.52,21.56 26.82,21.26 26.82,21.05 26.67,20.9 26.46,20.9 26.16,21.2 25.95,21.2 25.8,21.05 25.8,20.84 26.04,20.6 26.04,20.39 25.89,20.25 25.68,20.25 25.44,20.48 25.23,20.48 25.08,20.33 25.08,20.12 25.32,19.89 25.32,19.68 25.17,19.53 24.96,19.53 24.72,19.76 24.51,19.76 24.36,19.61 24.36,19.4 24.6,19.17 24.6,18.96 24.45,18.81 24.24,18.81 24.01,19.04 23.79,19.04 23.65,18.89 23.65,18.68 23.88,18.45 23.88,18.24 23.73,18.09 23.52,18.09 23.29,18.32 23.08,18.32 22.94,18.19 22.94,17.98 23.11,17.81 23.11,17.6 22.96,17.45 22.75,17.45 22.58,17.62 22.37,17.62 22.21,17.46 15.86,17.46 14.72,18.6 14.72,19.26 14.44,19.54 14.44,20.79 U4.F8
SEMC_WE: length 35.3
  TOP w0.127: U4.F9 14.81,19.66 15.1,19.36 15.1,18.86 16.12,17.84 16.85,17.84 17,17.99 17,18.45 17.15,18.6 17.36,18.6 17.51,18.45 17.51,17.99 17.65,17.84 17.87,17.84 18.01,17.99 18.01,18.45 18.16,18.6 18.37,18.6 18.52,18.45 18.52,17.99 18.67,17.84 18.88,17.84 19.03,17.99 19.03,18.45 19.18,18.6 19.39,18.6 19.54,18.45 19.54,17.99 19.69,17.84 19.9,17.84 20.05,17.99 20.05,18.45 20.19,18.6 20.41,18.6 20.55,18.45 20.55,17.99 20.7,17.84 20.91,17.84 21.06,17.99 21.06,18.45 21.21,18.6 21.42,18.6 21.57,18.45 21.57,17.99 21.72,17.84 21.94,17.84 22.09,17.99 22.09,18.74 22.71,19.35 22.92,19.35 23.09,19.18 23.3,19.18 23.45,19.33 23.45,19.54 23.28,19.71 23.28,19.92 23.43,20.07 23.64,20.07 23.81,19.9 24.02,19.9 24.17,20.05 24.17,20.26 24,20.43 24,20.64 24.15,20.79 24.36,20.79 24.53,20.62 24.74,20.62 24.89,20.77 24.89,20.98 24.72,21.15 24.72,21.36 24.87,21.51 25.08,21.51 25.25,21.34 25.46,21.34 25.61,21.49 25.61,21.7 25.44,21.87 25.44,22.08 25.58,22.23 25.79,22.23 25.96,22.06 26.17,22.06 26.32,22.21 26.32,22.42 26.15,22.59 26.15,22.8 26.4,23.05 35.29,23.05 35.54,23.29 U8.D1
SPDIF_IN: length 28.5
  TOP w0.127: U8.M12 v1(43.62,17.77)
  LYR03 w0.102: 44.85,15.68 44.27,16.26 44.27,17.15 43.65,17.77 v1(43.62,17.77)
  LYR03 w0.127: 44.85,15.68 46.24,14.29 48.79,14.29 49.82,15.32 51.87,15.32 52.55,16 v2(53.06,16)
  BOTTOM w0.127: v2(53.06,16) 52.83,15.77 52.83,8.21 47.97,3.34 J4.17
SPDIF_OUT: length 32.1
  TOP w0.127: U8.L11 v1(42.97,18.42)
  LYR03 w0.102: 46.09,20.03 46.08,20.04 43.46,20.04 43.3,19.88 43.3,18.74 v1(42.97,18.42)
  LYR03 w0.127: v2(52.55,16.61) 51.59,15.65 49.25,15.65 48.11,16.79 48.11,18.72 46.79,20.03 46.09,20.03
  BOTTOM w0.127: v2(52.55,16.61) 52.53,16.59 52.53,9.27 45.47,2.22 J4.16
SWD_CLK: length 44
  TOP w0.127: U8.F12 43.62,22.31 45.24,22.31 45.87,22.94 45.87,23.42 46.56,24.11 46.56,24.77 46.99,25.2 51.66,25.2 52.07,25.6 52.07,26.54 52.76,27.23 55.65,27.23 57.02,25.86 57.02,7.7 56.11,6.78 51.36,6.78 50.67,6.1 R43.1 R32.1
SWD_DIO: length 40.4
  TOP w0.102: 46.09,24.09 45.52,23.52 45.52,23.04 45.12,22.64 U8.E14
  TOP w0.127: R44.1 R49.2 53.77,6.15 54.1,6.48 56.31,6.48 57.33,7.49 57.33,25.99 55.8,27.51 52.63,27.51 51.82,26.7 51.82,25.71 51.58,25.48 46.79,25.48 46.3,25 46.3,24.31 46.09,24.09
UART1_RXD: length 22.1
  TOP w0.102: v2(45.9,18.62) 45.72,18.8 44.66,18.8 U8.L14
  TOP w0.127: R46.2 v2(52.53,32.64)
  BOTTOM w0.127: v2(45.9,18.62) 46.38,19.1 46.76,19.1 46.77,19.12 49.06,19.12 50.2,20.26 50.2,27.92 49.38,28.75 49.38,31.47 50.2,32.29 U10.6 52.18,32.29 v2(52.53,32.64)
UART1_TXD: length 22.2
  TOP w0.102: U8.K14 44.89,19.1 46.02,19.1 46.51,18.62 v2(46.63,18.62)
  TOP w0.127: v2(52.07,31.78) 52.2,31.9 R45.2
  BOTTOM w0.127: v2(52.07,31.78) 52.06,31.79 U10.5 50.36,31.79 49.61,31.04 49.61,28.84 50.43,28.02 50.43,21.86 50.67,21.62 50.67,19.23 50.27,18.82 46.94,18.82 46.74,18.62 v2(46.63,18.62)
USB_HOST_DN: length 5.2
  TOP w0.119: J1.2 6.04,30.56 v2(6.15,30.66) 6.53,30.28 7.32,30.28 7.48,30.11 U2.2
  BOTTOM w0.119: R131.2 7.72,30.69 L3.2 7.01,30.69 6.78,30.46 6.35,30.46 v2(6.15,30.66)
USB_HOST_DP: length 4.3
  TOP w0.119: J1.3 6.11,29.91 v2(6.12,29.9) 6.27,30.05 6.81,30.05 6.98,29.88 U2.1
  BOTTOM w0.119: v2(6.12,29.9) 6.3,30.08 6.78,30.08 7.02,29.84 L3.3
  BOTTOM w0.127: L3.3 7.71,29.84 R132.2
USB_HOST_OC: length 81.5
  TOP w0.127: U1.2 7.51,25.21 6.5,26.22 R6.2 6.24,26.29 6.09,26.14 v2(5.99,26.14) ; v2(45.42,17.93) 45.26,18.09 U8.M14
  LYR03 w0.127: v2(5.99,26.14) 6.09,26.14 7.12,27.17 7.12,33.41 8.86,35.16 47.7,35.16 49.38,33.48 52.43,33.48 v2(52.91,33.96)
  BOTTOM w0.102: v2(45.42,17.93) 45.73,18.24 46.79,18.24 47.04,18.49
  BOTTOM w0.127: 47.04,18.49 47.09,18.54 50.39,18.54 50.98,19.13 50.98,21.68 50.71,21.95 50.71,30.88 51.1,31.27 52.15,31.27 52.93,32.06 52.93,33.94 v2(52.91,33.96)
USB_HOST_PWR: length 60.8
  TOP w0.127: v1(45.53,24.92) 45.15,24.54 44.65,24.54 U8.B14 ; R7.2 8.74,24.44 U1.1 8.78,23.15 v2(8.76,23.14)
  BOTTOM w0.102: 45.75,26.35 45.75,25.13 v1(45.53,24.92)
  BOTTOM w0.127: 45.75,26.35 45.75,28.27 47.12,29.64 47.12,33.28 46.89,33.5 40.64,33.5 39.95,34.19 26.77,34.19 26.26,34.7 14.88,34.7 10.49,30.3 10.49,28.3 8.76,26.57 v2(8.76,23.14) R135.1
USB_OTG1_DN: length 42.1
  TOP w0.102: U8.M8 v1(40.37,18.42)
  LYR03 w0.102: 41.49,15.68 41.49,15.71 41.49,15.72 41.49,16.75 41.39,16.85 41.25,16.85 41.15,16.95 41.15,17.16 41.25,17.26 41.39,17.26 41.49,17.36 41.49,18.04 40.91,18.63 40.58,18.63 v1(40.37,18.42)
  LYR03 w0.119: 41.49,15.68 41.49,14.73 40.13,13.38 33.27,13.38 32.31,12.42 28.3,12.42 28.02,12.14 15.73,12.14 15.54,12.32 15.25,12.32 15.07,12.14 14.77,12.14 14.59,12.32 14.3,12.32 14.11,12.14 13.82,12.14 13.63,12.32 13.34,12.32 13.16,12.14 12.86,12.14 12.68,12.32 12.39,12.32 12.2,12.14 11.91,12.14 11.72,12.32 11.43,12.32 11.25,12.14 10.95,12.14 10.77,12.32 10.48,12.32 10.29,12.14 9.93,12.14 9.33,11.54 9.33,10.99 v2(9.16,10.81)
  BOTTOM w0.102: 8.1,10.82 R136.1
  BOTTOM w0.119: v2(9.16,10.81) 9.15,10.82 L4.1 8.49,10.82 8.1,10.82
USB_OTG1_DP: length 42
  TOP w0.102: U8.L8 v1(40.37,19.07)
  LYR03 w0.102: 41.73,15.68 41.73,15.71 41.72,15.72 41.72,18.14 41.01,18.85 40.58,18.85 v1(40.37,19.07)
  LYR03 w0.119: v2(9.17,9.96) 9.58,10.37 9.58,11.44 10.03,11.89 28.12,11.89 28.4,12.17 32.41,12.17 33.38,13.13 40.23,13.13 41.73,14.63 41.73,15.68
  BOTTOM w0.102: 8.1,9.96 R137.1
  BOTTOM w0.119: 8.1,9.96 8.49,9.96 L4.4 9.17,9.97 v2(9.17,9.96)
USB_OTG1_ID: length 62.6
  TOP w0.127: v2(7.42,20.3) 7.82,20.7 7.82,22.21 v2(6.79,23.24) ; 4.38,9.44 J2.4 5.8,9.44 5.98,9.26 v2(7.98,9.26) U3.3 ; U8.H10 v1(42.32,21.02)
  LYR03 w0.102: v1(42.32,21.02) 42.31,21.02 41.98,21.34 38.56,21.34 38.1,21.34 37.74,20.98 34.28,20.98
  LYR03 w0.127: v2(7.42,20.3) 6.17,19.05 6.17,15.22 7.87,13.51 7.87,9.37 v2(7.98,9.26) ; v2(10.15,18.14) 11.14,17.15 25.45,17.15 29.29,20.98 34.28,20.98
  BOTTOM w0.127: v2(7.42,20.3) 7.87,20.75 9.78,20.75 10.15,20.38 v2(10.15,18.14) ; R134.2 7.06,24 6.88,23.83 6.88,23.34 v2(6.79,23.24) 6.5,23.54 Q2.1
USB_OTG1_OC: length 57.4
  TOP w0.127: U8.G11 v1(42.97,21.67) ; U1.3 v2(6.24,25.48)
  LYR03 w0.102: v1(42.97,21.67) 42.65,21.99 40.77,21.99 40.12,22.64 39.54,22.64 39.4,22.79 39.4,22.83 39.4,22.83 39.4,25.25 40.26,26.11
  LYR03 w0.127: v2(6.24,25.48) 6.24,25.57 7.47,26.8 7.47,33.22 9.09,34.85 33.07,34.85 40.26,27.66 40.26,26.11
  BOTTOM w0.127: R133.2 7.39,25.43 7.2,25.62 6.38,25.62 v2(6.24,25.48)
USB_OTG2_DN: length 53.7
  TOP w0.102: 39.29,15.68 39.29,16.11 39.73,16.54 39.73,17.12 U8.N7
  TOP w0.127: 39.29,15.68 39.29,15.52 v2(39.71,15.1)
  LYR03 w0.119: v2(39.71,15.1) 39.3,15.54 36.29,15.54 35.67,14.92 33.43,14.92 32.38,15.96 29.6,15.96 27.43,13.79 23.47,13.79 21.76,15.5 10.95,15.5 9.28,17.17 9.28,19.16 9.65,19.53 9.65,28.2 9.38,28.47 8.64,28.47 v2(8.38,28.21)
  BOTTOM w0.119: v2(8.38,28.21) 8.64,28.47 9.19,28.47 9.76,29.05 9.76,30.52 9.6,30.69 L3.1 8.49,30.69 R131.1
USB_OTG2_DP: length 53.6
  TOP w0.102: v2(39.73,15.83) 39.73,16.16 40.05,16.48 U8.P7
  LYR03 w0.102: v2(39.73,15.83) 39.69,15.79
  LYR03 w0.119: v2(8.38,28.99) 8.65,28.72 9.48,28.72 9.9,28.3 9.9,19.43 9.53,19.06 9.53,17.27 11.05,15.75 11.99,15.75 12.11,15.87 12.11,15.96 12.23,16.08 12.47,16.08 12.59,15.96 12.59,15.87 12.71,15.75 12.95,15.75 13.07,15.87 13.07,15.96 13.19,16.08 13.43,16.08 13.55,15.96 13.55,15.87 13.67,15.75 13.9,15.75 14.02,15.87 14.02,15.96 14.14,16.08 14.38,16.08 14.5,15.96 14.5,15.87 14.62,15.75 14.86,15.75 14.98,15.87 14.98,15.96 15.1,16.08 15.34,16.08 15.46,15.96 15.46,15.87 15.58,15.75 15.81,15.75 15.93,15.87 15.93,15.96 16.05,16.08 16.29,16.08 16.41,15.96 16.41,15.87 16.53,15.75 16.77,15.75 16.89,15.87 16.89,15.96 17.01,16.08 17.25,16.08 17.37,15.96 17.37,15.87 17.49,15.75 17.72,15.75 17.84,15.87 17.84,15.96 17.96,16.08 18.2,16.08 18.32,15.96 18.32,15.87 18.44,15.75 18.68,15.75 18.8,15.87 18.8,15.96 18.92,16.08 19.16,16.08 19.28,15.96 19.28,15.87 19.4,15.75 19.63,15.75 19.75,15.87 19.75,15.93 19.87,16.05 20.11,16.05 20.23,15.93 20.23,15.87 20.35,15.75 21.86,15.75 23.57,14.04 27.33,14.04 29.5,16.21 32.49,16.21 33.53,15.17 35.56,15.17 36.18,15.79 39.69,15.79
  BOTTOM w0.119: v2(8.38,28.99) 8.52,28.85 8.53,28.85 8.54,28.84 8.54,28.84 8.66,28.72 9.08,28.72 9.51,29.14 9.51,29.61 9.28,29.84 L3.4 8.49,29.84 R132.1
USB_OTG_DN: length 4.9
  TOP w0.119: 4.38,10.74 J2.2 5.92,10.74 v2(5.94,10.77) 6.35,10.36 7.29,10.36 7.48,10.17 U3.2
  BOTTOM w0.119: R136.2 7.18,10.82 L4.2 5.99,10.82 v2(5.94,10.77)
USB_OTG_DP: length 3.9
  TOP w0.119: 4.38,10.09 J2.3 5.94,10.09 v2(5.97,10.06) 6.12,9.91 U3.1
  BOTTOM w0.102: L4.3 6.65,9.96 R137.2
  BOTTOM w0.119: v2(5.97,10.06) 6.07,9.97 L4.3
USER_BUTTON: length 17.8
  TOP w0.127: v2(49.46,16.11) 49.12,16.45 R31.2 49.13,16.8 R33.2 49.13,18.61 C33.1
  TOP w0.254: U8.L6 v1(39.07,18.42)
  LYR03 w0.102: 46.09,20.29 46.08,20.3 42.27,20.3 42.01,20.04 40.24,20.04 39.34,20.04 39.07,19.77 v1(39.07,18.42)
  LYR03 w0.127: 46.09,20.29 47,20.29 48.69,18.59 48.69,16.88 v2(49.46,16.11)
USER_LED_B: length 12.7
  TOP w0.127: U8.G10 v1(42.32,21.67) ; v1(46.46,23.17) 46.46,23.55 46.84,23.93 46.84,24.51 47.19,24.87 R48.2
  BOTTOM w0.102: v1(42.32,21.67) 42.65,21.99 43.33,21.99 43.84,22.51 45.8,22.51 46.09,22.8
  BOTTOM w0.127: 46.09,22.8 v1(46.46,23.17)
USER_LED_G: length 4.2
  TOP w0.127: R29.2 46.91,21.74 46.63,21.46 46.63,21.01 46.41,20.78 46,20.78 45.76,21.02 44.27,21.02 U8.G13
USER_LED_R: length 3.3
  TOP w0.102: 46.09,22.71 46.06,22.71 45.34,21.99 U8.F14
  TOP w0.127: R27.2 47.29,23.47 46.53,22.71 46.09,22.71
WDOG_B: length 51.3
  TOP w0.127: C16.1 23.56,7.26 v2(23.62,7.19) ; U8.D14 v1(44.92,22.97)
  LYR03 w0.102: 46.09,23.01 44.97,23.01 v1(44.92,22.97)
  LYR03 w0.127: v2(23.62,7.19) 23.62,7.29 24.12,7.79 36.02,7.79 36.04,7.81 39.74,7.81 42.65,10.72 51.89,10.72 v2(53.26,12.09) ; v2(51.94,20.88) 50.47,20.88 49.23,22.12 47.4,22.12 46.72,22.8 46.3,22.8 46.09,23.01
  BOTTOM w0.127: v2(53.26,12.09) 53.26,15.47 53.9,16.11 53.9,20.14 53.16,20.88 v2(51.94,20.88)
N1426169: length 30.3
  TOP w0.381: v2(38.86,12.42) 38.89,12.4 D3.2 38.59,11.59 38.1,11.1 38.1,7.7 41.3,4.5 46.13,4.5 v2(48.23,6.61)
  LYR03 w0.381: v2(58.17,7.6) 55.5,7.6 54.51,6.61 v2(48.23,6.61)
  BOTTOM w0.381: R92.1 39.04,12.6 v2(38.86,12.42) ; D11.2 57.86,7.91 v2(58.17,7.6) 58.52,7.24 R64.2
N1428044: length 9.2
  TOP w0.127: R22.1 42.63,7.31 C24.1 41.66,8.06 R21.2 40.64,7.29 R20.2 39.88,9.98 40.34,10.44 U9.3
N1428076: length 5.1
  TOP w0.305: 42.9,8.64 43.08,8.46 43.28,8.46 ; 42.9,8.64 42.88,8.66 42.88,9.12 42.2,9.79 U9.2 ; 42.9,8.64 R22.2 43.28,8.46 ; 43.28,8.46 R24.1
N1428666: length 9.8
  TOP w0.127: U8.P11 42.72,16.72 42.72,16.31 43.25,15.77 44.07,15.77 45.09,14.76 R25.1 45.1,14.17 R26.1 45.79,13.37 45.8,13.36 C26.1 45.8,12.98 46.18,12.6 46.18,10.39 45.94,10.15 X2.3
N1428682: length 0.7
  TOP w0.203: U8.M2 36.78,18.09 36.7,18.01 36.23,18.01 U8.M1
N1428736: length 8.5
  TOP w0.127: X2.1 47.08,12 46.56,12.53 C27.1 46.56,14.17 R26.2 46.56,14.33 46.04,14.85 45.58,14.85 44.37,16.05 43.41,16.05 42.98,16.48 42.98,17.11 U8.N11
N1428810: length 6
  TOP w0.127: X1.1 43.29,13.46 43.14,13.62 42.33,13.62 42.15,13.79 C25.1 41.91,14.4 41.91,16.41 41.68,16.64 41.68,17.11 U8.N9
N1428818: length 3.5
  TOP w0.203: U8.K3 v1(37.12,19.07)
  BOTTOM w0.102: v1(37.12,19.07) 36.8,18.74 36.8,18.03 C71.1 36.03,17.8 35.66,17.42 R103.1
N1428874: length 4.9
  TOP w0.127: X1.2 40.25,13.3 40.54,13.59 41.17,13.59 41.39,13.81 C23.1 41.43,14.19 41.43,16.49 41.35,16.56 U8.P9
N1430764: length 3.4
  TOP w0.305: v2(16.87,12.75) 16.87,11.69 16.51,11.33 U5.2
  BOTTOM w0.203: R124.1 16.87,13.54 v2(16.87,12.75)
N1431030: length 2.6
  TOP w0.305: U5.7 18.08,11.33 R9.1 R10.2
N1431040: length 18.2
  TOP w0.127: R12.2 R13.2 22.81,5.49 22.58,5.26 20.72,5.26 20.5,5.49 U6.2 20.5,6.51 19.58,7.42 19.58,9.35 19.74,9.5 20.68,9.5 21.46,10.29 21.46,12.09 20.83,12.73 19.96,12.73 19.81,12.57 C12.1
  TOP w0.203: C12.1 19.18,12.22 18.95,11.99 18.08,11.99 U5.8 17.86,11.98 17.65,12.19 v2(17.65,12.78)
  BOTTOM w0.203: v2(17.65,12.78) 17.66,12.78 R124.2
N1431138: length 2.9
  TOP w0.203: U5.1 15.45,12.69 v2(15.32,12.83)
  BOTTOM w0.203: v2(15.32,12.83) 15.39,12.91 C101.1 15.39,14.48 TP3.1
N1431606: length 2.4
  TOP w0.127: D2.2 24.03,8.97 R14.1 24.35,8.21 24.32,8.18 C16.2
N1435220: length 15.8
  TOP w0.254: U8.J6 v1(39.07,20.37)
  GND05 w0.305: v2(39.49,27.79) 40.34,26.95 40.34,21.36 39.93,20.96 39.62,20.96 39.07,20.41 v1(39.07,20.37)
  BOTTOM w0.203: v1(39.07,20.37) 39.07,19.98 C67.1
  BOTTOM w0.305: v2(39.49,27.79) 39.5,27.8 39.5,28.35 38.99,28.86 38.53,28.86 36.91,30.48 C72.1 R97.2
N1441990: length 1.5
  TOP w0.127: v1(43.62,17.12) U8.N12
  BOTTOM w0.203: v1(43.62,17.12) 44.19,17.68 TP1.1
N1446802: length 2.1
  TOP w0.127: U7.A5 33.62,8.14 34.19,7.57 v1(34.19,7.41)
  BOTTOM w0.102: 34.19,7.42 v1(34.19,7.41)
  BOTTOM w0.127: R102.2 34.85,6.89 34.33,7.41 v1(34.19,7.41)
N1446884: length 1.7
  TOP w0.127: U7.A2 34.06,10.49 v1(34.24,10.49)
  BOTTOM w0.127: R99.2 v1(34.24,10.49)
N1454429: length 5
  TOP w0.127: U1.4 4.39,24.4 4.05,24.07 v2(4.05,23.88) 3.84,23.88 3.51,23.55 R2.2 R3.1 R4.2
  BOTTOM w0.127: Q2.3 v2(4.05,23.88)
N1538445: length 1.4
  TOP w0.127: SW1.8 49.16,33.16 R39.2
N1538449: length 1.4
  TOP w0.127: SW1.7 50.53,31.88 R40.2
N1538453: length 1.4
  TOP w0.127: R41.2 50.53,30.61 SW1.6
N1538457: length 1.4
  TOP w0.127: R42.2 49.16,29.35 SW1.5
N1582760: length 5.3
  TOP w0.127: SW4.2 SW4.4 50.23,7.53 R34.1
N1582904: length 7.4
  TOP w0.127: SW3.2 SW3.4 51.16,12.3 R36.1 49.96,13.56 R35.1 C35.1
N1658417: length 5.3
  TOP w0.127: SW2.2 54.89,17.5 51.92,17.5 51.73,17.69 SW2.4 49.93,17.69 R33.1
N1660774: length 4.1
  TOP w0.127: U8.F13 44.27,21.67 45.47,21.67 45.66,21.87 46.54,21.87 46.79,22.12 46.79,22.51 46.89,22.61 R28.1
N1700883: length 1.5
  TOP w0.381: LED1.2 3.1,18.09 3.48,18.47 R1.2
N1720722: length 3.6
  TOP w0.127: R27.1 48.12,23.41 LED2.1
N1720728: length 3.5
  TOP w0.127: R48.1 53.42,22.73 54.29,21.86 LED2.3
N1720734: length 3.6
  TOP w0.127: LED2.4 48.17,21.86 R29.1
N1744694: length 8.1
  TOP w0.305: J5.49 60.65,31.71 60.05,32.31 59.45,32.31 59.32,32.44 56.28,32.44 56.25,32.41 56.17,32.41 55.72,31.96 R54.2
N1744704: length 6.3
  TOP w0.127: J5.50 61.7,32.21 61.16,32.74 R55.2 60.77,34.15 59.78,33.16 R53.1
N1790471: length 9.3
  TOP w0.127: R13.1 22.05,6.18 21.81,6.42 21.8,6.42 21.66,6.56 21.66,6.56 21.44,6.78 21.44,7.58 U6.3 20.5,8.81 21.72,10.03 21.72,11.05 22.61,11.94 D1.1 ; D1.1 D2.1 ; D1.1 22.6,12.37
N1791257: length 1.2
  TOP w0.102: U8.N10 v1(42.32,17.12)
  BOTTOM w0.102: TP2.1 42.62,16.82 v1(42.32,17.12)
N1827694: length 3.6
  BOTTOM w0.305: U13.4 13.36,10.49 13.54,10.67 C102.2 ; C102.2 R126.2 ; C102.2 R125.1
N1830761: length 3.5
  BOTTOM w0.305: R122.2 R123.1 ; R122.2 C92.2 ; R122.2 20.47,10.2 U12.4

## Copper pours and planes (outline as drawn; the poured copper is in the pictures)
3V3_LCD on TOP: 60.38,29.82 58.5,29.82 58.37,29.69 58.37,28.78 58.45,28.7 60.6,28.7 61.47,29.57 62.94,29.57 62.97,29.59 62.97,29.82 62.94,29.85 61.52,29.85 61.47,29.9 61.47,30.02 61.52,30.08 62.97,30.08 62.99,30.1 62.99,30.3 62.94,30.35 60.91,30.35
5V_HOST on TOP: 4.19,31.09 4.19,31.35 6.1,33.25 6.99,33.25 7.24,33 7.24,31.09 7.11,30.96 5.08,30.96 4.95,31.09
5V_LCD on TOP: 58.45,31.27 58.45,30.74 58.5,30.68 60.96,30.68 61.06,30.58 62.77,30.58 62.79,30.61 62.79,30.84 62.77,30.86 61.52,30.86 61.5,30.89 61.5,31.04 61.52,31.07 62.77,31.07 62.79,31.09 62.79,31.35 62.77,31.37 58.55,31.37
5V_OTG on TOP: 12.98,38.51 11.86,38.51 11.48,38.13 11.48,36.4 10.85,35.76 10.85,33.96 11.07,33.73 11.53,33.73 13.28,35.49 13.28,38.2
5V_OTG on TOP: 6.2,11.2 6.78,10.62 7.04,10.62 7.11,10.69 7.11,11.1 7.29,11.28 7.29,12.22 7.44,12.37 7.44,13.36 7.21,13.59 5.89,13.59 5.74,13.44 5.74,13.03 4.32,11.61 4.32,11.28 4.39,11.2
5V_OTG on BOTTOM: 15.16,4.37 15.47,4.07 16.61,4.07 16.84,4.29 16.84,5.06 16.79,5.11 16.05,5.11 15.85,5.31 15.85,7.67 15.8,7.72 15.19,7.72 15.16,7.7
5V_OTG on PWR04: 12.66,6.4 12.66,5.88 12.95,5.59 15.57,5.59 16.05,5.11 16.66,5.11 17.12,4.65 17.12,4.27 16.21,3.35 13.87,3.35 13.34,2.82 13.34,1.68 13,1.35 11.73,1.35 11.53,1.55 11.53,3.86 2.62,12.78 2.62,33.78 5.59,36.76 11.13,36.76 11.53,37.16 11.53,38.46 11.68,38.61 12.98,38.61 13.13,38.46 13.13,35.82 12.65,35.33 6.05,35.33 4.88,34.16 4.88,14.19
5V_USB_HOST on TOP: 8.48,17.83 8.74,17.58 9.58,17.58 9.75,17.76 9.75,19.76 10.27,20.28 10.27,32.63 9.55,33.35 8.05,33.35 7.98,33.28 7.98,32.54 8.05,32.46 8.99,32.46 9.26,32.2 9.26,21.2 8.48,20.42
5V_USB_HOST on BOTTOM: 9.35,17.55 8.18,17.55 7.9,17.83 7.9,19.94 8.36,20.4 9.4,20.4 9.6,20.19 9.6,17.81
5V_USB_OTG on TOP: 57.66,31.35 56.14,31.35 55.93,31.55 55.58,31.55 55.45,31.42 55.45,31.42 54.94,30.91 54.94,30.53 55.17,30.3 56.69,30.3 57.07,30.68 57.69,30.68 57.76,30.76 57.76,31.24
5V_USB_OTG on TOP: 8.08,13.44 8.08,12.93 8.19,12.82 8.83,12.82 9.12,13.11 9.88,13.11 9.93,13.16 9.93,16.16 9.14,16.94 8.66,16.94 7.8,17.81 7.8,19.43 7.7,19.53 7.29,19.53 7.21,19.46 7.21,18.34 6.68,17.81 6.68,17.4 7.47,16.61 7.47,14.05
5V_USB_OTG on BOTTOM: 10.13,13.87 10.41,13.59 10.41,12.83 10.57,12.68 10.87,12.68 11,12.8 11,14.48 10.9,14.58 10.9,17.35 10.64,17.6 9.96,17.6 9.35,16.99 9.35,15.37 9.6,15.11 9.91,15.11 10.13,14.89
5V_USB_OTG on PWR04: 6.68,17.47 6.76,17.39 7.65,17.39 7.79,17.52 7.79,18.27 7.67,18.39 6.86,18.39 6.68,18.21
GND on BOTTOM (solid shape): 41.1,21.16 41.1,20.78 41.07,20.75 40.79,20.75 40.67,20.63 40.67,20.27 40.92,20.02 41.1,20.02 41.15,19.97 41.15,19.61 41.12,19.58 40.97,19.58 40.39,20.17 40.28,20.17 40.18,20.27 40.18,21.16 40.23,21.21 41.05,21.21
GND on TOP: 7.85,30.63 7.85,31.37 7.54,31.68 7.54,32.08 7.62,32.16 8.86,32.16 8.99,32.03 8.99,31.12 8.92,31.04 8.2,31.04 8.1,30.94 8.1,30.63 8.05,30.58 7.9,30.58
GND on TOP: 10.62,13.11 14.3,13.11 14.43,13.23 17.81,13.23 18.05,12.99 20.92,12.99 20.98,13.06 24.33,13.06 24.89,13.62 24.89,13.72 24.84,13.77 13.89,13.77 10.92,16.74 10.52,16.74 10.34,16.56 10.34,13.39
GND on TOP: 8.08,33.71 7.92,33.86 7.92,35.71 9.02,36.81 9.02,38.33 9.22,38.53 10.41,38.53 10.77,38.18 10.77,36.17 10.36,35.76 10.36,33.4 10.29,33.33 10.01,33.33 9.63,33.71
GND on TOP: 18.49,10.85 17.5,10.85 17.4,10.95 16.36,10.95 16.26,10.85 16.26,10.31 16.15,10.21 14.33,10.21 14,9.88 14,8.28 14.35,7.93 15.75,7.93 16.15,7.52 16.51,7.52 16.59,7.6 16.59,7.75 16.31,8.03 16.31,9.3 16.54,9.53 17.17,9.53 17.27,9.63 17.27,10.36 17.4,10.49 18.49,10.49 18.57,10.57 18.57,10.77
GND on TOP: 31.32,15.95 31.32,16.56 31.6,16.84 31.6,17.27 31.34,17.53 30.94,17.53 29.11,15.7 29.11,15.24 29.18,15.17 29.77,15.17 29.92,15.32 30.05,15.32 30.18,15.44 30.18,15.72 30.3,15.85 31.22,15.85
GND on TOP: 7.47,27.81 8.74,27.81 8.92,27.64 8.92,26.95 8.71,26.75 7.59,26.75 7.21,27.13 7.21,27.56
GND on TOP: 8.33,9.09 8.33,10.97 8.28,11.03 8.15,11.03 8.13,11 8.13,10.67 8.05,10.59 7.92,10.59 7.85,10.67 7.85,11.1 7.77,11.18 7.77,12.17 7.9,12.3 8.88,12.3 9.01,12.17 9.01,11.32 8.78,11.1 8.78,9.81 9.45,9.15 9.45,6.43 9.47,6.4 9.57,6.3 11.33,6.3 11.48,6.15 11.48,5.49 11.38,5.39 8.69,5.39 8.09,5.98 8.09,8.85
GND on TOP: 6.05,19.56 5.94,19.46 5.94,18.16 5.71,17.93 4.24,17.93 3.96,17.65 3.96,15.19 4.7,14.45 5.69,14.45 5.84,14.61 5.84,17.32 6.53,18.01 6.53,19.46 6.43,19.56
GND on TOP: 10.6,32.7 11.42,32.7 13.16,34.44 34.04,34.44 38.13,30.35 38.13,29.69 38.63,29.19 38.63,28.58 38.53,28.47 38.4,28.47 34.92,31.95 14.2,31.95 10.72,28.47 10.57,28.47 10.53,28.51 10.53,32.63
GND on TOP: 22.07,20.75 20.73,20.75 20.55,20.58 20.55,19.33 20.68,19.2 21.54,19.2 22.23,19.89 22.23,20.6
GND on BOTTOM: 17.23,7.9 17.06,7.72 16.54,7.72 16.46,7.65 16.46,7.04 16.54,6.96 17.86,6.96 18.03,7.14 18.03,8 18.21,8.18 18.21,10.57 17.82,10.96 16.48,10.96 16.25,10.73 16.25,9.82 16.48,9.59 17.21,9.59 17.5,9.3 17.5,8.66 17.23,8.4
GND on BOTTOM: 22.2,13.51 24.18,13.51 24.61,13.08 24.61,12.22 24.56,12.17 24.26,12.17 23.93,12.5 23.19,12.5 22.89,12.8 22.23,12.8 22.12,12.9 22.12,13.44
GND on BOTTOM: 10.74,31.19 14.38,34.82 14.38,35.51 14.12,35.76 8.08,35.76 7.87,35.56 7.87,31.42 8.1,31.19
GND on BOTTOM: 42.11,15.27 42.11,14.56 42.27,14.4 42.98,14.4 43.1,14.53 43.1,16 43.18,16.08 43.59,16.08 43.71,15.95 43.71,15.85 43.81,15.75 47.27,15.75 47.32,15.7 47.32,15.32 47.12,15.11 43.76,15.11 43.68,15.2 43.52,15.2 43.38,15.06 43.38,14.45 43.66,14.17 43.81,14.17 44.45,13.54 44.45,12.12 43.61,11.28 40.36,11.28 40.13,11.51 40.13,12.14 40.01,12.27 39.67,12.27 39.52,12.42 39.52,13.82 40.13,14.43 41.27,14.43 41.45,14.61 41.45,15.27 41.55,15.37 42.01,15.37
GND on BOTTOM: outline of 104 points within 3.94,5.64 36.27,33.86 ; 5 cut-outs
GND on BOTTOM: 34.54,17.58 31.8,17.58 29.79,15.57 29.79,15.34 29.84,15.29 30.07,15.29 30.3,15.52 32.08,15.52 32.36,15.8 32.36,16.74 32.54,16.92 33.27,16.92 33.48,17.12 34.52,17.12 34.59,17.2 34.59,17.53
GND on BOTTOM: 14.68,7.27 14.27,7.27 14.22,7.22 14.22,5.82 12.41,4 9.86,4 9.84,4.01 9.54,4.01 8.99,3.47 8.99,1.51 9.16,1.35 10.54,1.35 10.74,1.55 10.74,2.74 11.25,3.25 14.12,3.25 14.73,3.86 14.73,7.22
GND on GND02: 4.14,13.95 1.75,16.33 1.75,22.58 4.11,24.94 4.11,33.28 6.1,35.26 6.1,38.28 6.53,38.71 61.65,38.71 62.18,38.18 62.18,35.84 62.19,35.83 62.19,35.22 62.2,35.21 62.2,34.39 63.86,32.74 66.64,32.74 67.01,32.37 67.01,8.21 65.94,7.14 63.12,7.14 61.98,6 61.98,1.65 61.57,1.25 6.5,1.25 6.15,1.6 6.15,4.04 4.14,6.05 ; 10 cut-outs
GND on LYR03: 19.81,32.82 22.63,32.82 23.34,33.53 34.06,33.53 40.03,27.56 40.03,26.47 39.19,25.63 39.19,24.87 38.99,24.66 36.98,24.66 36.7,24.39 36.7,21.29 36.6,21.19 29.01,21.19 25.3,17.48 11.58,17.48 10.39,18.67 10.39,31.8 12.12,33.53 19.1,33.53
GND on GND05: 4.14,13.95 3.37,14.72 3.37,24.2 4.11,24.94 4.11,33.28 6.1,35.26 6.1,38.28 6.53,38.71 61.65,38.71 62.18,38.18 62.18,35.84 62.19,35.83 62.19,35.22 63.93,33.48 66.14,33.48 67.01,32.62 67.01,30.44 66.96,30.4 65.78,30.4 65.71,30.33 65.71,29.15 65.84,29.02 66.86,29.02 67.01,28.87 67.01,16.24 66.9,16.14 65.74,16.14 65.6,16 65.6,14.83 64.88,14.11 64.14,14.11 63.98,13.95 63.98,11.98 64.35,11.61 66.8,11.61 67.01,11.4 67.01,8.68 66.19,7.86 63.84,7.86 61.98,6 61.98,1.65 61.57,1.25 6.5,1.25 6.15,1.6 6.15,4.04 4.14,6.05 ; 10 cut-outs
GND_EARTH on TOP: 65.11,0.26 65.07,0.26 64.97,0.25 3.26,0.25 2.98,0.26 2.93,0.26 2.75,0.27 2.45,0.32 2.13,0.41 1.96,0.47 1.7,0.6 1.46,0.75 1.29,0.88 0.99,1.16 0.42,2.14 0.29,2.75 0.25,3.06 0.25,37.02 0.26,37.08 0.28,37.29 0.3,37.43 0.4,37.81 0.47,38 0.63,38.33 0.79,38.57 1.11,38.95 1.42,39.2 1.83,39.45 2.25,39.62 2.82,39.73 3.04,39.75 64.9,39.75 65.42,39.69 66,39.53 66.78,39.05 67.32,38.42 67.66,37.64 67.72,37.34 67.73,37.26 67.74,37.15 67.74,2.85 67.69,2.57 67.41,1.74 67.31,1.56 67,1.15 66.91,1.06 66.58,0.78 66.27,0.59 66.13,0.52 65.82,0.39 65.62,0.34 65.5,0.31 65.31,0.28 65.26,0.27 ; 1 cut-out
GND_EARTH on BOTTOM: 65.11,0.26 65.07,0.26 64.97,0.25 3.26,0.25 2.98,0.26 2.93,0.26 2.75,0.27 2.45,0.32 2.13,0.41 1.96,0.47 1.7,0.6 1.46,0.75 1.29,0.88 0.99,1.16 0.42,2.14 0.29,2.75 0.25,3.06 0.25,37.02 0.26,37.08 0.28,37.29 0.3,37.43 0.4,37.81 0.47,38 0.63,38.33 0.79,38.57 1.11,38.95 1.42,39.2 1.83,39.45 2.25,39.62 2.82,39.73 3.04,39.75 64.9,39.75 65.42,39.69 66,39.53 66.78,39.05 67.32,38.42 67.66,37.64 67.72,37.34 67.73,37.26 67.74,37.15 67.74,2.85 67.69,2.57 67.41,1.74 67.31,1.56 67,1.15 66.91,1.06 66.58,0.78 66.27,0.59 66.13,0.52 65.82,0.39 65.62,0.34 65.5,0.31 65.31,0.28 65.26,0.27 ; 1 cut-out
GND_EARTH on BOTTOM: 67.13,15.9 67.41,15.9 67.54,15.77 67.54,12.17 67.34,11.96 65.28,11.96 64.95,12.3 64.95,13.84 66.01,14.91 66.83,14.91 66.83,15.6
GND_EARTH on BOTTOM: 1.02,21.62 2.29,21.62 2.59,21.31 2.59,17.4 2.46,17.27 1.17,17.27 1.02,17.43
GND_EARTH on GND02: 3.04,39.75 64.9,39.75 65.42,39.69 66,39.53 66.78,39.05 67.32,38.42 67.66,37.64 67.72,37.34 67.73,37.26 67.74,37.15 67.74,2.85 67.69,2.57 67.41,1.74 67.31,1.56 67,1.15 66.91,1.06 66.58,0.78 66.27,0.59 66.13,0.52 65.82,0.39 65.62,0.34 65.5,0.31 65.31,0.28 65.26,0.27 65.11,0.26 65.07,0.26 64.97,0.25 2.98,0.26 2.93,0.26 2.75,0.27 2.45,0.32 2.13,0.41 1.96,0.47 1.7,0.6 1.46,0.75 1.29,0.88 0.99,1.16 0.42,2.14 0.29,2.75 0.25,3.06 0.25,37.02 0.26,37.08 0.28,37.29 0.3,37.43 0.4,37.81 0.47,38 0.63,38.33 0.79,38.57 1.11,38.95 1.42,39.2 1.83,39.45 2.25,39.62 2.82,39.73 ; 1 cut-out
GND_EARTH on GND05: 65.11,0.26 65.07,0.26 64.97,0.25 3.26,0.25 2.98,0.26 2.93,0.26 2.75,0.27 2.45,0.32 2.13,0.41 1.96,0.47 1.7,0.6 1.46,0.75 1.29,0.88 0.99,1.16 0.42,2.14 0.29,2.75 0.25,3.06 0.25,37.02 0.26,37.08 0.28,37.29 0.3,37.43 0.4,37.81 0.47,38 0.63,38.33 0.79,38.57 1.11,38.95 1.42,39.2 1.83,39.45 2.25,39.62 2.82,39.73 3.04,39.75 64.9,39.75 65.42,39.69 66,39.53 66.78,39.05 67.32,38.42 67.66,37.64 67.72,37.34 67.73,37.26 67.74,37.15 67.74,2.85 67.69,2.57 67.41,1.74 67.31,1.56 67,1.15 66.91,1.06 66.58,0.78 66.27,0.59 66.13,0.52 65.82,0.39 65.62,0.34 65.5,0.31 65.31,0.28 65.26,0.27 ; 1 cut-out
VDD_SOC_IN on BOTTOM (solid shape): 41.96,21.16 41.96,19.56 41.91,19.51 41.63,19.51 41.58,19.56 41.58,20.04 41.43,20.19 40.97,20.19 40.84,20.32 40.84,20.5 40.92,20.58 41.48,20.58 41.53,20.63 41.53,21.19 41.58,21.24 41.88,21.24
VDD_SOC_IN on BOTTOM (solid shape): 40.93,22.59 41.19,22.59 41.26,22.51 41.26,22.17 41.25,22.14 41.21,22.12 40.96,22.12 40.64,22.44 40.12,22.44 39.87,22.18 39.76,22.18 39.4,21.82 39.4,21.49 39.56,21.33 39.67,21.33 39.8,21.21 39.8,20.78 39.75,20.73 38.86,20.73 38.72,20.86 38.73,21.02 38.72,21.08 38.72,21.22 38.55,21.4 38.21,21.4 38.16,21.45 38.16,21.8 38.21,21.85 38.75,21.85 38.93,22.03 38.96,22.03 38.97,22.03 39.24,22.06 39.38,22.29 39.38,22.31 39.38,22.49 39.56,22.66 39.69,22.66 39.9,22.72 40.02,22.9 40.04,22.92 40.6,22.92
